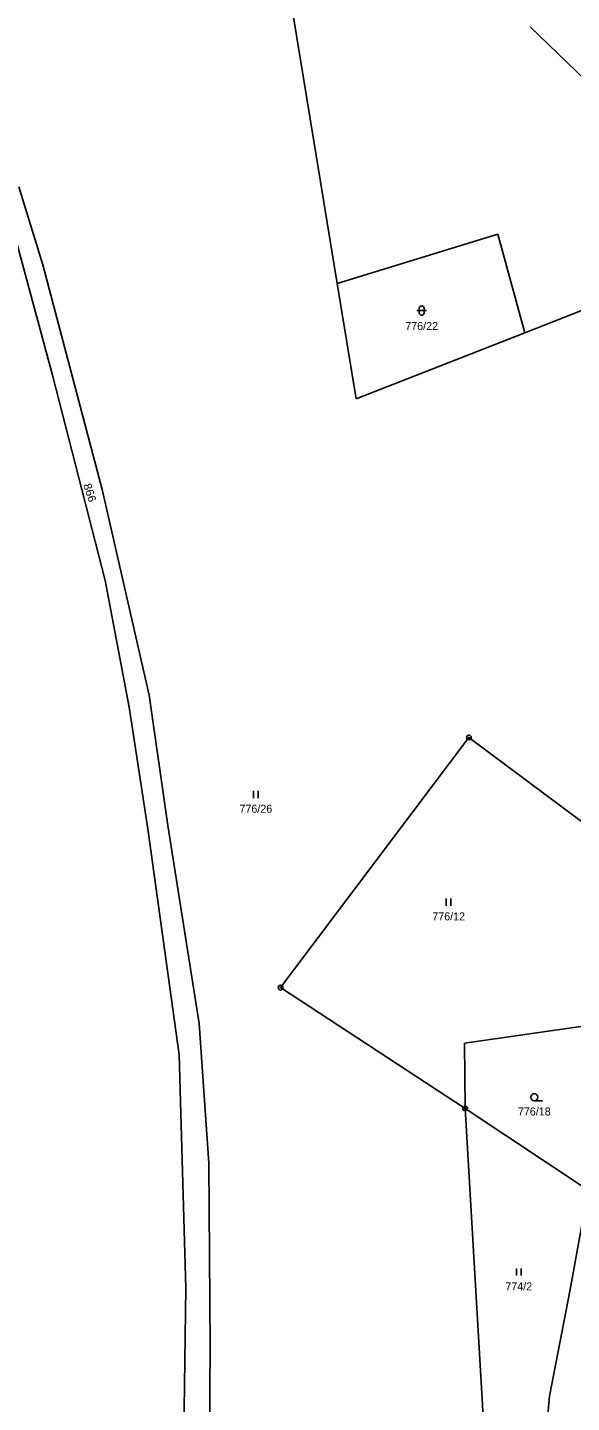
# Model space of a CAD drawing. Extents: x -739410 to -735662, y -942282 to -940043.
# Drawn here: x -737798.5 to -737683.1, y -941020 to -940728 of the extents above; entities that cross this region are included whole.
import ezdxf
from ezdxf.enums import TextEntityAlignment as Align

# ---------------------------------------------------------------- set-up
doc = ezdxf.new("R2010")
doc.units = 0
doc.header["$LTSCALE"] = 0.68
for name, color, linetype, lineweight in [('1', 7, 'Continuous', 25), ('3', 7, 'Continuous', 25), ('8', 7, 'Continuous', 25)]:
    doc.layers.add(name, color=color, linetype=linetype, lineweight=lineweight)
doc.layers.add('2', color=7, linetype='Continuous')

msp = doc.modelspace()

# ---------------------------------------------------------------- linework, layer by layer
at = {"layer": '1'}
for p, q in [((-737745.55, -940704.54), (-737732.8, -940782.36)), ((-737691.83, -940727.87), (-737680.14, -940739.12)), ((-737800.36, -940761.82), (-737795.25, -940778.4)), ((-737793.2, -940801.8), (-737803.19, -940764.9)), ((-737732.8, -940782.36), (-737698.71, -940771.85)), ((-737698.71, -940771.85), (-737692.99, -940792.81)), ((-737782.7, -940826.13), (-737795.25, -940778.4)), ((-737732.8, -940782.36), (-737728.78, -940806.88)), ((-737692.99, -940792.81), (-737678.43, -940787.09)), ((-737728.78, -940806.88), (-737692.99, -940792.81)), ((-737782.06, -940845.46), (-737793.2, -940801.8)), ((-737772.72, -940869.8), (-737782.7, -940826.13)), ((-737776.94, -940872.35), (-737782.06, -940845.46)), ((-737768.74, -940897.49), (-737772.72, -940869.8)), ((-737772.97, -940898.13), (-737776.94, -940872.35)), ((-737704.84, -940878.74), (-737744.83, -940931.89)), ((-737666.96, -940907.05), (-737704.84, -940878.74)), ((-737766.31, -940946.14), (-737772.97, -940898.13)), ((-737762.09, -940939.48), (-737768.74, -940897.49)), ((-737744.83, -940931.89), (-737705.67, -940957.52)), ((-737760.05, -940969.15), (-737762.09, -940939.48)), ((-737680.62, -940940.1), (-737705.76, -940943.66)), ((-737705.76, -940943.66), (-737705.67, -940957.52)), ((-737764.9, -940995.7), (-737766.31, -940946.14)), ((-737679.55, -940974.9), (-737705.67, -940957.52)), ((-737705.67, -940957.52), (-737697.81, -941091.85)), ((-737759.79, -941008.2), (-737760.05, -940969.15)), ((-737683.34, -940996.01), (-737679.55, -940974.9)), ((-737766.44, -941100.66), (-737764.9, -940995.7)), ((-737687.75, -941018.67), (-737683.34, -940996.01)), ((-737760.05, -941043.44), (-737759.79, -941008.2)), ((-737693, -941075.26), (-737687.75, -941018.67))]:
    msp.add_line(p, q, dxfattribs=at)
at = {"layer": '3'}
for p, q in [((-737715.871, -940788.111), (-737713.869, -940788.111)), ((-737715.371, -940787.611), (-737715.371, -940788.612)), ((-737714.369, -940788.612), (-737714.369, -940787.611)), ((-737750.581, -940891.62), (-737750.581, -940890.12)), ((-737749.58, -940891.62), (-737749.58, -940890.12)), ((-737709.651, -940914.48), (-737709.651, -940912.98)), ((-737708.65, -940914.48), (-737708.65, -940912.98)), ((-737690.963, -940955.91), (-737689.213, -940955.91)), ((-737694.771, -940993.05), (-737694.771, -940991.55)), ((-737693.77, -940993.05), (-737693.77, -940991.55))]:
    msp.add_line(p, q, dxfattribs=at)
msp.add_circle((-737690.9629, -940955.1598), 0.75, dxfattribs=at)
for centre, start, end in [((-737714.87, -940787.6109), 0, 180), ((-737714.87, -940788.6109), 180, 359.98789)]:
    msp.add_arc(centre, 0.5, start, end, dxfattribs=at)
at = {"layer": '8'}
for centre, radius in [((-737704.84, -940878.7399), 0.5), ((-737704.84, -940878.7399), 0.0303), ((-737744.83, -940931.8899), 0.5), ((-737744.83, -940931.8899), 0.0303), ((-737705.67, -940957.5199), 0.5), ((-737705.67, -940957.5199), 0.0303)]:
    msp.add_circle(centre, radius, dxfattribs=at)

# ---------------------------------------------------------------- texts
at = {"layer": '2'}
for s, p in [('776/22', (-737714.87, -940792.235)), ('776/26', (-737750.07, -940894.745)), ('776/12', (-737709.14, -940917.605)), ('776/18', (-737690.97, -940959.035)), ('774/2', (-737694.26, -940996.175))]:
    msp.add_text(s, height=1.7, dxfattribs=at).set_placement(p, align=Align.CENTER)
at = {"layer": '2', "width": 1.05}
msp.add_text('866', height=1.7, rotation=288, dxfattribs=at).set_placement((-737786.1101, -940827.0343), align=Align.CENTER)

doc.saveas('drawing.dxf')
